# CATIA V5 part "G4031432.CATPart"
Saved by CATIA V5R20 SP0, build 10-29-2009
Part number: G4031432
Revision: 3
Definition: design
Nomenclature: G4031432
Source: made
Description: NOT SPECIFIED
Bounding box of the stored display mesh (mm): x -16 to 16, y -11.818 to 11.818, z -12 to 12
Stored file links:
  C:\Users\Raffaele\Desktop\3D X SITO CF\BOLEX\27-BUSH REF 403\G4031432.CATPart
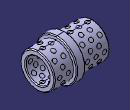
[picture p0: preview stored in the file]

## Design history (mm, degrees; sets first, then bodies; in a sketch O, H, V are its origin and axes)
Body1 "MANIFOLD_SOLID_BREP #8525" (main body)
  Solid1: solid without history
Body2 "MANIFOLD_SOLID_BREP #8668"
  Solid2: solid without history
Body3 "MANIFOLD_SOLID_BREP #8811"
  Solid3: solid without history
Body4 "MANIFOLD_SOLID_BREP #8954"
  Solid4: solid without history
Body5 "MANIFOLD_SOLID_BREP #9097"
  Solid5: solid without history
Body6 "MANIFOLD_SOLID_BREP #9240"
  Solid6: solid without history
Body7 "MANIFOLD_SOLID_BREP #9383"
  Solid7: solid without history
Body8 "MANIFOLD_SOLID_BREP #9528"
  Solid8: solid without history
Body9 "MANIFOLD_SOLID_BREP #9673"
  Solid9: solid without history
Body10 "MANIFOLD_SOLID_BREP #9818"
  Solid10: solid without history
Body11 "MANIFOLD_SOLID_BREP #9963"
  Solid11: solid without history
Body12 "MANIFOLD_SOLID_BREP #10106"
  Solid12: solid without history
Body13 "MANIFOLD_SOLID_BREP #10249"
  Solid13: solid without history
Body14 "MANIFOLD_SOLID_BREP #10394"
  Solid14: solid without history
Body15 "MANIFOLD_SOLID_BREP #10539"
  Solid15: solid without history
Body16 "MANIFOLD_SOLID_BREP #10684"
  Solid16: solid without history
Body17 "MANIFOLD_SOLID_BREP #10829"
  Solid17: solid without history
Body18 "MANIFOLD_SOLID_BREP #10974"
  Solid18: solid without history
Body19 "MANIFOLD_SOLID_BREP #11119"
  Solid19: solid without history
Body20 "MANIFOLD_SOLID_BREP #11264"
  Solid20: solid without history
Body21 "MANIFOLD_SOLID_BREP #11409"
  Solid21: solid without history
Body22 "MANIFOLD_SOLID_BREP #11554"
  Solid22: solid without history
Body23 "MANIFOLD_SOLID_BREP #11699"
  Solid23: solid without history
Body24 "MANIFOLD_SOLID_BREP #11844"
  Solid24: solid without history
Body25 "MANIFOLD_SOLID_BREP #11989"
  Solid25: solid without history
Body26 "MANIFOLD_SOLID_BREP #12132"
  Solid26: solid without history
Body27 "MANIFOLD_SOLID_BREP #12277"
  Solid27: solid without history
Body28 "MANIFOLD_SOLID_BREP #12422"
  Solid28: solid without history
Body29 "MANIFOLD_SOLID_BREP #12565"
  Solid29: solid without history
Body30 "MANIFOLD_SOLID_BREP #12710"
  Solid30: solid without history
Body31 "MANIFOLD_SOLID_BREP #12855"
  Solid31: solid without history
Body32 "MANIFOLD_SOLID_BREP #12998"
  Solid32: solid without history
Body33 "MANIFOLD_SOLID_BREP #13141"
  Solid33: solid without history
Body34 "MANIFOLD_SOLID_BREP #13284"
  Solid34: solid without history
Body35 "MANIFOLD_SOLID_BREP #13427"
  Solid35: solid without history
Body36 "MANIFOLD_SOLID_BREP #13572"
  Solid36: solid without history
Body37 "MANIFOLD_SOLID_BREP #13717"
  Solid37: solid without history
Body38 "MANIFOLD_SOLID_BREP #13862"
  Solid38: solid without history
Body39 "MANIFOLD_SOLID_BREP #14007"
  Solid39: solid without history
Body40 "MANIFOLD_SOLID_BREP #14150"
  Solid40: solid without history
Body41 "MANIFOLD_SOLID_BREP #14293"
  Solid41: solid without history
Body42 "MANIFOLD_SOLID_BREP #14438"
  Solid42: solid without history
Body43 "MANIFOLD_SOLID_BREP #14583"
  Solid43: solid without history
Body44 "MANIFOLD_SOLID_BREP #14728"
  Solid44: solid without history
Body45 "MANIFOLD_SOLID_BREP #14873"
  Solid45: solid without history
Body46 "MANIFOLD_SOLID_BREP #15018"
  Solid46: solid without history
Body47 "MANIFOLD_SOLID_BREP #15163"
  Solid47: solid without history
Body48 "MANIFOLD_SOLID_BREP #15308"
  Solid48: solid without history
Body49 "MANIFOLD_SOLID_BREP #15453"
  Solid49: solid without history
Body50 "MANIFOLD_SOLID_BREP #15598"
  Solid50: solid without history
Body51 "MANIFOLD_SOLID_BREP #15743"
  Solid51: solid without history
Body52 "MANIFOLD_SOLID_BREP #15888"
  Solid52: solid without history
Body53 "MANIFOLD_SOLID_BREP #16033"
  Solid53: solid without history
Body54 "MANIFOLD_SOLID_BREP #16176"
  Solid54: solid without history
Body55 "MANIFOLD_SOLID_BREP #16319"
  Solid55: solid without history
Body56 "MANIFOLD_SOLID_BREP #16462"
  Solid56: solid without history
Body57 "MANIFOLD_SOLID_BREP #16605"
  Solid57: solid without history
Body58 "MANIFOLD_SOLID_BREP #16750"
  Solid58: solid without history
Body59 "MANIFOLD_SOLID_BREP #16895"
  Solid59: solid without history
Body60 "MANIFOLD_SOLID_BREP #17040"
  Solid60: solid without history
Body61 "MANIFOLD_SOLID_BREP #17185"
  Solid61: solid without history
Body62 "MANIFOLD_SOLID_BREP #17330"
  Solid62: solid without history
Body63 "MANIFOLD_SOLID_BREP #17475"
  Solid63: solid without history
Body64 "MANIFOLD_SOLID_BREP #17620"
  Solid64: solid without history
Body65 "MANIFOLD_SOLID_BREP #17765"
  Solid65: solid without history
